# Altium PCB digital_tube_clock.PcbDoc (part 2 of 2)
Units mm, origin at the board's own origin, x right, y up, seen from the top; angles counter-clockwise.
Board outline 78.99 x 94.23 mm, 2 copper layers (Top Layer, Bottom Layer); 32 components, 49 nets, 189 pads, 6 vias.
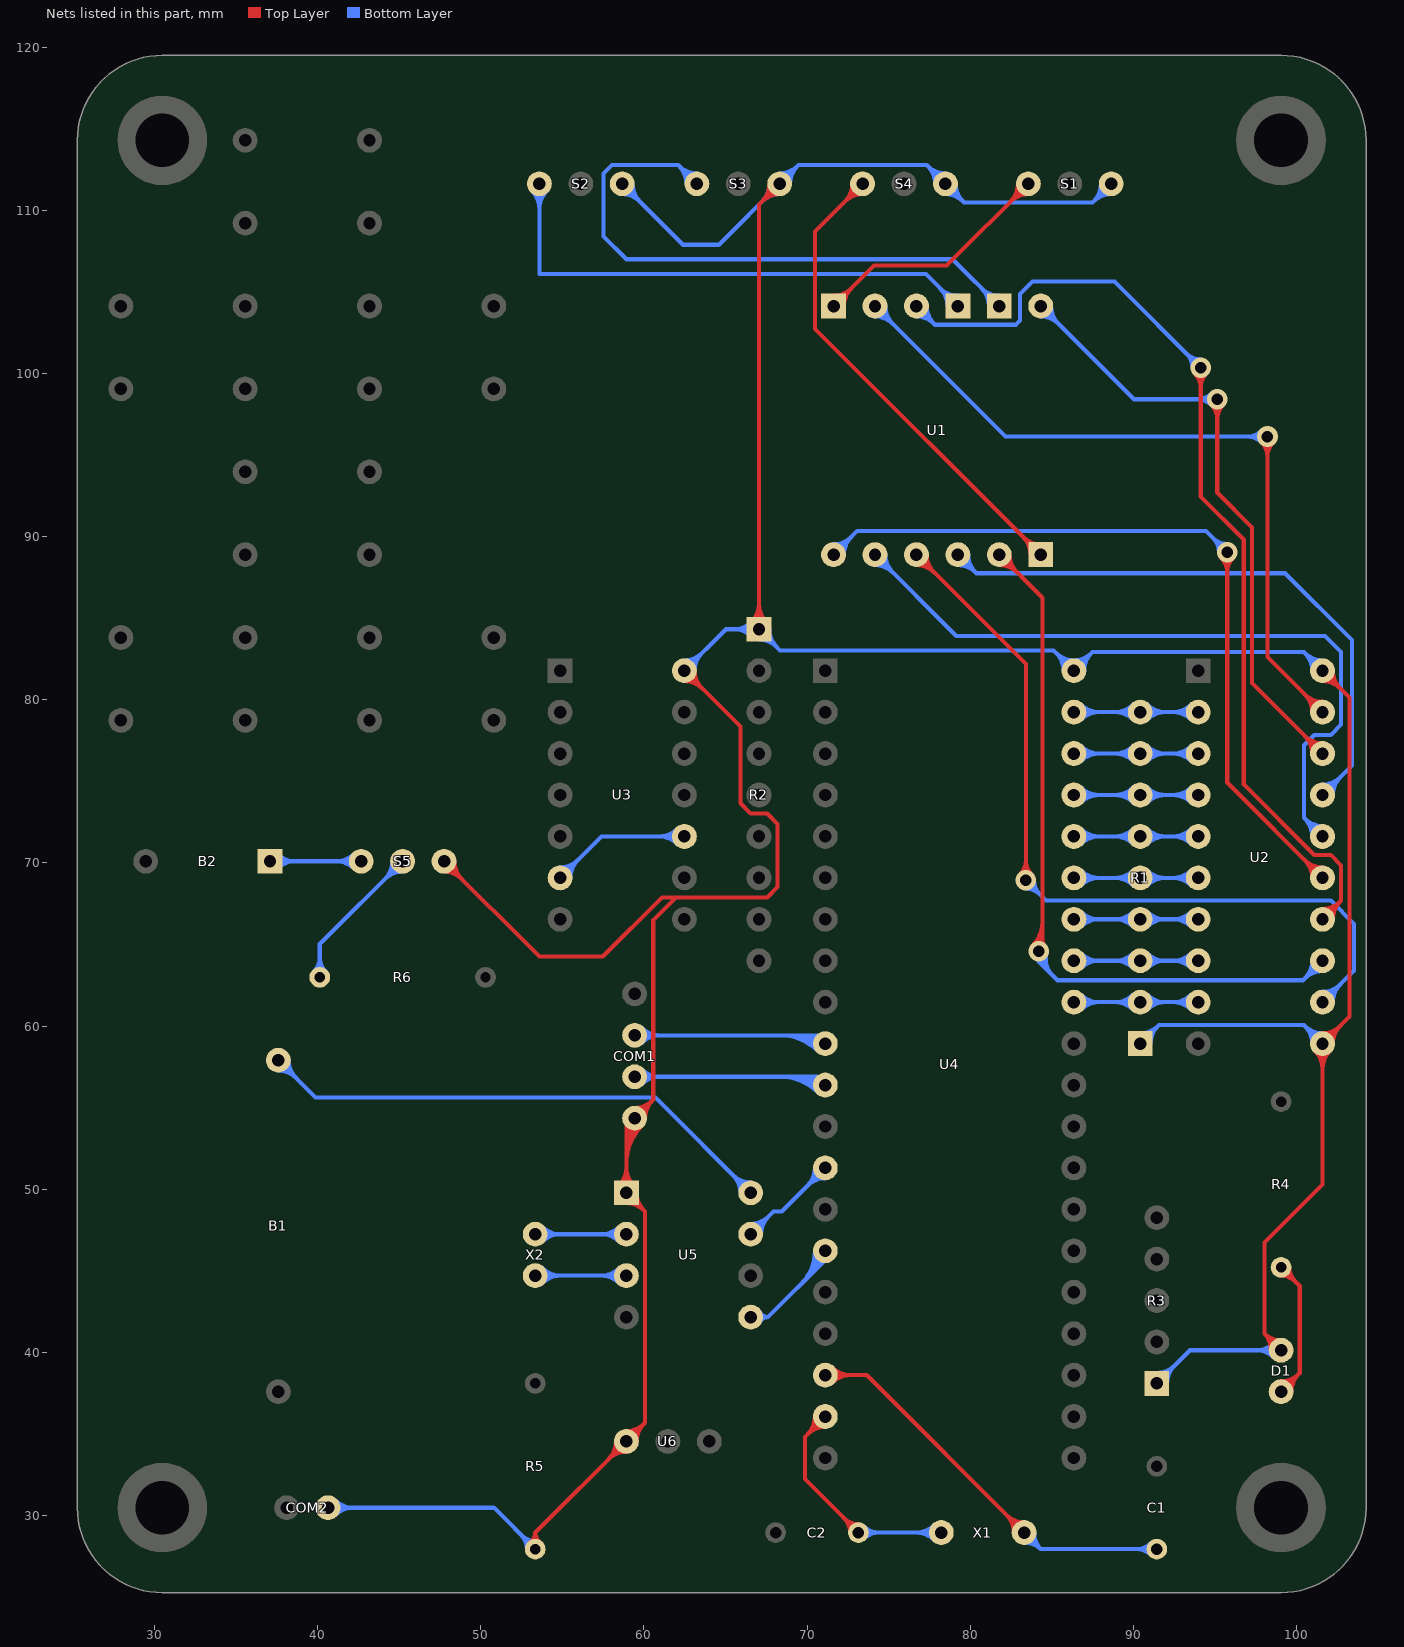
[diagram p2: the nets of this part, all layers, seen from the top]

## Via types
v1: diameter 1.27, hole 0.711, Top Layer to Bottom Layer, 6 vias

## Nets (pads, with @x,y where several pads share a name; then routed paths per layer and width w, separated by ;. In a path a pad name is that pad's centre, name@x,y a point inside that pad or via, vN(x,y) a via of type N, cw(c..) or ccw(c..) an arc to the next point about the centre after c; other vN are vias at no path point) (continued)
NetB1_VCC: B1.VCC U5.8 | length 40
  Bottom Layer w0.254: B1.VCC@37.592,57.277 cw(c37.592,55.744) 38.676,56.828 cw(c39.76,57.912) B1.VCC@38.227,57.912 ; B1.VCC@37.592,57.531 cw(c37.592,56.611) 38.242,57.262 cw(c38.893,57.912) B1.VCC@37.973,57.912 ; B1.VCC@37.592,57.912 39.878,55.626 60.706,55.626 U5.8@66.548,49.784 ; U5.8@65.913,49.784 ccw(c64.38,49.784) 65.464,50.868 ccw(c66.548,51.952) U5.8@66.548,50.419 ; U5.8@66.167,49.784 ccw(c65.247,49.784) 65.898,50.434 ccw(c66.548,51.085) U5.8@66.548,50.165
NetB2_1: B2.1 S5.e | length 13.3
  Bottom Layer w0.254: B2.1@37.084,70.104 S5.e@42.672,70.104 ; B2.1@37.353,69.835 cw(c38.004,69.184) 38.004,70.104 cw(c38.004,71.024) B2.1@37.353,70.373 ; B2.1@37.533,69.655 cw(c38.617,68.571) 38.617,70.104 cw(c38.617,71.637) B2.1@37.533,70.553 ; S5.e@42.223,69.655 ccw(c41.139,68.571) 41.139,70.104 ccw(c41.139,71.637) S5.e@42.223,70.553 ; S5.e@42.403,69.835 ccw(c41.752,69.184) 41.752,70.104 ccw(c41.752,71.024) S5.e@42.403,70.373
NetD1_2: D1.2 R4.1 | length 14.3
  Top Layer w0.254: D1.2@99.06,37.592 100.203,38.735 100.203,44.069 R4.1@99.06,45.212 ; D1.2@99.06,37.973 ccw(c99.06,38.893) 99.71,38.242 ccw(c100.361,37.592) D1.2@99.441,37.592 ; D1.2@99.06,38.227 ccw(c99.06,39.76) 100.144,38.676 ccw(c101.228,37.592) D1.2@99.695,37.592 ; R4.1@99.06,44.704 cw(c99.06,43.478) 99.927,44.345 cw(c100.794,45.212) R4.1@99.568,45.212
NetR1_2: R1.2 U2.9 U4.32 | length 23
  Bottom Layer w0.254: U4.32@86.36,61.468 R1.2@90.424,61.468 U2.9@93.98,61.468 ; U4.32@86.629,61.199 cw(c87.28,60.548) 87.28,61.468 cw(c87.28,62.388) U4.32@86.629,61.737 ; U4.32@86.809,61.019 cw(c87.893,59.935) 87.893,61.468 cw(c87.893,63.001) U4.32@86.809,61.917 ; R1.2@89.975,61.019 ccw(c88.891,59.935) 88.891,61.468 ccw(c88.891,63.001) R1.2@89.975,61.917 ; R1.2@90.155,61.199 ccw(c89.504,60.548) 89.504,61.468 ccw(c89.504,62.388) R1.2@90.155,61.737 ; R1.2@90.693,61.199 cw(c91.344,60.548) 91.344,61.468 cw(c91.344,62.388) R1.2@90.693,61.737 ; R1.2@90.873,61.019 cw(c91.957,59.935) 91.957,61.468 cw(c91.957,63.001) R1.2@90.873,61.917 ; U2.9@93.531,61.019 ccw(c92.447,59.935) 92.447,61.468 ccw(c92.447,63.001) U2.9@93.531,61.917 ; U2.9@93.711,61.199 ccw(c93.06,60.548) 93.06,61.468 ccw(c93.06,62.388) U2.9@93.711,61.737
NetR1_3: R1.3 U2.8 U4.33 | length 23
  Bottom Layer w0.254: U4.33@86.36,64.008 R1.3@90.424,64.008 U2.8@93.98,64.008 ; U4.33@86.629,63.739 cw(c87.28,63.088) 87.28,64.008 cw(c87.28,64.928) U4.33@86.629,64.277 ; U4.33@86.809,63.559 cw(c87.893,62.475) 87.893,64.008 cw(c87.893,65.541) U4.33@86.809,64.457 ; R1.3@89.975,63.559 ccw(c88.891,62.475) 88.891,64.008 ccw(c88.891,65.541) R1.3@89.975,64.457 ; R1.3@90.155,63.739 ccw(c89.504,63.088) 89.504,64.008 ccw(c89.504,64.928) R1.3@90.155,64.277 ; R1.3@90.693,63.739 cw(c91.344,63.088) 91.344,64.008 cw(c91.344,64.928) R1.3@90.693,64.277 ; R1.3@90.873,63.559 cw(c91.957,62.475) 91.957,64.008 cw(c91.957,65.541) R1.3@90.873,64.457 ; U2.8@93.531,63.559 ccw(c92.447,62.475) 92.447,64.008 ccw(c92.447,65.541) U2.8@93.531,64.457 ; U2.8@93.711,63.739 ccw(c93.06,63.088) 93.06,64.008 ccw(c93.06,64.928) U2.8@93.711,64.277
NetR1_4: R1.4 U2.7 U4.34 | length 23
  Bottom Layer w0.254: U4.34@86.36,66.548 R1.4@90.424,66.548 U2.7@93.98,66.548 ; U4.34@86.629,66.279 cw(c87.28,65.628) 87.28,66.548 cw(c87.28,67.468) U4.34@86.629,66.817 ; U4.34@86.809,66.099 cw(c87.893,65.015) 87.893,66.548 cw(c87.893,68.081) U4.34@86.809,66.997 ; R1.4@89.975,66.099 ccw(c88.891,65.015) 88.891,66.548 ccw(c88.891,68.081) R1.4@89.975,66.997 ; R1.4@90.155,66.279 ccw(c89.504,65.628) 89.504,66.548 ccw(c89.504,67.468) R1.4@90.155,66.817 ; R1.4@90.693,66.279 cw(c91.344,65.628) 91.344,66.548 cw(c91.344,67.468) R1.4@90.693,66.817 ; R1.4@90.873,66.099 cw(c91.957,65.015) 91.957,66.548 cw(c91.957,68.081) R1.4@90.873,66.997 ; U2.7@93.531,66.099 ccw(c92.447,65.015) 92.447,66.548 ccw(c92.447,68.081) U2.7@93.531,66.997 ; U2.7@93.711,66.279 ccw(c93.06,65.628) 93.06,66.548 ccw(c93.06,67.468) U2.7@93.711,66.817
NetR1_5: R1.5 U2.6 U4.35 | length 23
  Bottom Layer w0.254: U4.35@86.36,69.088 R1.5@90.424,69.088 U2.6@93.98,69.088 ; U4.35@86.629,68.819 cw(c87.28,68.168) 87.28,69.088 cw(c87.28,70.008) U4.35@86.629,69.357 ; U4.35@86.809,68.639 cw(c87.893,67.555) 87.893,69.088 cw(c87.893,70.621) U4.35@86.809,69.537 ; R1.5@89.975,68.639 ccw(c88.891,67.555) 88.891,69.088 ccw(c88.891,70.621) R1.5@89.975,69.537 ; R1.5@90.155,68.819 ccw(c89.504,68.168) 89.504,69.088 ccw(c89.504,70.008) R1.5@90.155,69.357 ; R1.5@90.693,68.819 cw(c91.344,68.168) 91.344,69.088 cw(c91.344,70.008) R1.5@90.693,69.357 ; R1.5@90.873,68.639 cw(c91.957,67.555) 91.957,69.088 cw(c91.957,70.621) R1.5@90.873,69.537 ; U2.6@93.531,68.639 ccw(c92.447,67.555) 92.447,69.088 ccw(c92.447,70.621) U2.6@93.531,69.537 ; U2.6@93.711,68.819 ccw(c93.06,68.168) 93.06,69.088 ccw(c93.06,70.008) U2.6@93.711,69.357
NetR1_6: R1.6 U2.5 U4.36 | length 23
  Bottom Layer w0.254: U4.36@86.36,71.628 R1.6@90.424,71.628 U2.5@93.98,71.628 ; U4.36@86.629,71.359 cw(c87.28,70.708) 87.28,71.628 cw(c87.28,72.548) U4.36@86.629,71.897 ; U4.36@86.809,71.179 cw(c87.893,70.095) 87.893,71.628 cw(c87.893,73.161) U4.36@86.809,72.077 ; R1.6@89.975,71.179 ccw(c88.891,70.095) 88.891,71.628 ccw(c88.891,73.161) R1.6@89.975,72.077 ; R1.6@90.155,71.359 ccw(c89.504,70.708) 89.504,71.628 ccw(c89.504,72.548) R1.6@90.155,71.897 ; R1.6@90.693,71.359 cw(c91.344,70.708) 91.344,71.628 cw(c91.344,72.548) R1.6@90.693,71.897 ; R1.6@90.873,71.179 cw(c91.957,70.095) 91.957,71.628 cw(c91.957,73.161) R1.6@90.873,72.077 ; U2.5@93.531,71.179 ccw(c92.447,70.095) 92.447,71.628 ccw(c92.447,73.161) U2.5@93.531,72.077 ; U2.5@93.711,71.359 ccw(c93.06,70.708) 93.06,71.628 ccw(c93.06,72.548) U2.5@93.711,71.897
NetR1_7: R1.7 U2.4 U4.37 | length 23
  Bottom Layer w0.254: U4.37@86.36,74.168 R1.7@90.424,74.168 U2.4@93.98,74.168 ; U4.37@86.629,73.899 cw(c87.28,73.248) 87.28,74.168 cw(c87.28,75.088) U4.37@86.629,74.437 ; U4.37@86.809,73.719 cw(c87.893,72.635) 87.893,74.168 cw(c87.893,75.701) U4.37@86.809,74.617 ; R1.7@89.975,73.719 ccw(c88.891,72.635) 88.891,74.168 ccw(c88.891,75.701) R1.7@89.975,74.617 ; R1.7@90.155,73.899 ccw(c89.504,73.248) 89.504,74.168 ccw(c89.504,75.088) R1.7@90.155,74.437 ; R1.7@90.693,73.899 cw(c91.344,73.248) 91.344,74.168 cw(c91.344,75.088) R1.7@90.693,74.437 ; R1.7@90.873,73.719 cw(c91.957,72.635) 91.957,74.168 cw(c91.957,75.701) R1.7@90.873,74.617 ; U2.4@93.531,73.719 ccw(c92.447,72.635) 92.447,74.168 ccw(c92.447,75.701) U2.4@93.531,74.617 ; U2.4@93.711,73.899 ccw(c93.06,73.248) 93.06,74.168 ccw(c93.06,75.088) U2.4@93.711,74.437
NetR1_8: R1.8 U2.3 U4.38 | length 23
  Bottom Layer w0.254: U4.38@86.36,76.708 R1.8@90.424,76.708 U2.3@93.98,76.708 ; U4.38@86.629,76.439 cw(c87.28,75.788) 87.28,76.708 cw(c87.28,77.628) U4.38@86.629,76.977 ; U4.38@86.809,76.259 cw(c87.893,75.175) 87.893,76.708 cw(c87.893,78.241) U4.38@86.809,77.157 ; R1.8@89.975,76.259 ccw(c88.891,75.175) 88.891,76.708 ccw(c88.891,78.241) R1.8@89.975,77.157 ; R1.8@90.155,76.439 ccw(c89.504,75.788) 89.504,76.708 ccw(c89.504,77.628) R1.8@90.155,76.977 ; R1.8@90.693,76.439 cw(c91.344,75.788) 91.344,76.708 cw(c91.344,77.628) R1.8@90.693,76.977 ; R1.8@90.873,76.259 cw(c91.957,75.175) 91.957,76.708 cw(c91.957,78.241) R1.8@90.873,77.157 ; U2.3@93.531,76.259 ccw(c92.447,75.175) 92.447,76.708 ccw(c92.447,78.241) U2.3@93.531,77.157 ; U2.3@93.711,76.439 ccw(c93.06,75.788) 93.06,76.708 ccw(c93.06,77.628) U2.3@93.711,76.977
NetR1_9: R1.9 U2.2 U4.39 | length 23
  Bottom Layer w0.254: U4.39@86.36,79.248 R1.9@90.424,79.248 U2.2@93.98,79.248 ; U4.39@86.629,78.979 cw(c87.28,78.328) 87.28,79.248 cw(c87.28,80.168) U4.39@86.629,79.517 ; U4.39@86.809,78.799 cw(c87.893,77.715) 87.893,79.248 cw(c87.893,80.781) U4.39@86.809,79.697 ; R1.9@89.975,78.799 ccw(c88.891,77.715) 88.891,79.248 ccw(c88.891,80.781) R1.9@89.975,79.697 ; R1.9@90.155,78.979 ccw(c89.504,78.328) 89.504,79.248 ccw(c89.504,80.168) R1.9@90.155,79.517 ; R1.9@90.693,78.979 cw(c91.344,78.328) 91.344,79.248 cw(c91.344,80.168) R1.9@90.693,79.517 ; R1.9@90.873,78.799 cw(c91.957,77.715) 91.957,79.248 cw(c91.957,80.781) R1.9@90.873,79.697 ; U2.2@93.531,78.799 ccw(c92.447,77.715) 92.447,79.248 ccw(c92.447,80.781) U2.2@93.531,79.697 ; U2.2@93.711,78.979 ccw(c93.06,78.328) 93.06,79.248 ccw(c93.06,80.168) U2.2@93.711,79.517
NetR6_2: R6.2 S5.b | length 15
  Bottom Layer w0.254: R6.2@39.773,63.351 ccw(c38.906,64.218) 40.132,64.218 ccw(c41.358,64.218) R6.2@40.491,63.351 ; R6.2@40.132,62.992 40.132,65.024 S5.b@45.212,70.104 ; S5.b@44.577,70.104 cw(c43.044,70.104) 44.128,69.02 cw(c45.212,67.936) S5.b@45.212,69.469 ; S5.b@44.831,70.104 cw(c43.911,70.104) 44.562,69.454 cw(c45.212,68.803) S5.b@45.212,69.723
NetU1_a: U1.a U2.19 | length 57.2
  Top Layer w0.254: v1@97.863,95.78 cw(c96.995,94.913) 98.222,94.913 cw(c99.448,94.913) v1@98.581,95.78 ; v1(98.222,96.139) 98.222,82.626 U2.19@101.6,79.248 ; U2.19@100.965,79.248 ccw(c99.432,79.248) 100.516,80.332 ccw(c101.6,81.416) U2.19@101.6,79.883 ; U2.19@101.219,79.248 ccw(c100.299,79.248) 100.95,79.898 ccw(c101.6,80.549) U2.19@101.6,79.629
  Bottom Layer w0.254: U1.a@74.168,103.505 cw(c74.168,101.972) 75.252,103.056 cw(c76.336,104.14) U1.a@74.803,104.14 ; U1.a@74.168,103.759 cw(c74.168,102.839) 74.818,103.49 cw(c75.469,104.14) U1.a@74.549,104.14 ; U1.a@74.168,104.14 82.169,96.139 v1(98.222,96.139) ; v1@97.863,95.78 ccw(c96.995,94.913) 96.995,96.139 ccw(c96.995,97.365) v1@97.863,96.498
NetU1_b: U1.b U2.18 | length 49.1
  Top Layer w0.254: v1@94.789,98.066 cw(c93.922,97.199) 95.148,97.199 cw(c96.375,97.199) v1@95.508,98.066 ; v1(95.148,98.425) 95.148,92.71 97.282,90.576 97.282,81.026 U2.18@101.6,76.708 ; U2.18@100.965,76.708 ccw(c99.432,76.708) 100.516,77.792 ccw(c101.6,78.876) U2.18@101.6,77.343 ; U2.18@101.219,76.708 ccw(c100.299,76.708) 100.95,77.358 ccw(c101.6,78.009) U2.18@101.6,77.089
  Bottom Layer w0.254: U1.b@84.328,103.505 cw(c84.328,101.972) 85.412,103.056 cw(c86.496,104.14) U1.b@84.963,104.14 ; U1.b@84.328,103.759 cw(c84.328,102.839) 84.978,103.49 cw(c85.629,104.14) U1.b@84.709,104.14 ; U1.b@84.328,104.14 90.043,98.425 v1(95.148,98.425) ; v1@94.789,98.066 ccw(c93.922,97.199) 93.922,98.425 ccw(c93.922,99.651) v1@94.789,98.784
NetU1_c: U1.c U2.17 | length 44.3
  Bottom Layer w0.254: U1.c@79.248,88.265 cw(c79.248,86.732) 80.332,87.816 cw(c81.416,88.9) U1.c@79.883,88.9 ; U1.c@79.248,88.519 cw(c79.248,87.599) 79.898,88.25 cw(c80.549,88.9) U1.c@79.629,88.9 ; U1.c@79.248,88.9 80.391,87.757 99.314,87.757 103.403,83.668 103.403,75.971 U2.17@101.6,74.168 ; U2.17@101.6,74.549 ccw(c101.6,75.469) 102.25,74.818 ccw(c102.901,74.168) U2.17@101.981,74.168 ; U2.17@101.6,74.803 ccw(c101.6,76.336) 102.684,75.252 ccw(c103.768,74.168) U2.17@102.235,74.168
NetU1_d: U1.d U2.16 | length 52.1
  Bottom Layer w0.254: U1.d@74.168,88.265 cw(c74.168,86.732) 75.252,87.816 cw(c76.336,88.9) U1.d@74.803,88.9 ; U1.d@74.168,88.519 cw(c74.168,87.599) 74.818,88.25 cw(c75.469,88.9) U1.d@74.549,88.9 ; U1.d@74.168,88.9 79.146,83.922 101.752,83.922 102.743,82.931 102.743,78.486 102.108,77.851 101.092,77.851 100.457,77.216 100.457,72.771 U2.16@101.6,71.628 ; U2.16@100.965,71.628 ccw(c99.432,71.628) 100.516,72.712 ccw(c101.6,73.796) U2.16@101.6,72.263 ; U2.16@101.219,71.628 ccw(c100.299,71.628) 100.95,72.278 ccw(c101.6,72.929) U2.16@101.6,72.009
NetU1_e: U1.e U2.15 | length 59.2
  Top Layer w0.254: v1@95.399,88.693 cw(c94.532,87.826) 95.758,87.826 cw(c96.984,87.826) v1@96.117,88.693 ; v1(95.758,89.052) 95.758,74.93 U2.15@101.6,69.088 ; U2.15@100.965,69.088 ccw(c99.432,69.088) 100.516,70.172 ccw(c101.6,71.256) U2.15@101.6,69.723 ; U2.15@101.219,69.088 ccw(c100.299,69.088) 100.95,69.738 ccw(c101.6,70.389) U2.15@101.6,69.469
  Bottom Layer w0.254: U1.e@71.628,88.9 73.076,90.348 94.463,90.348 v1(95.758,89.052) ; U1.e@71.628,89.281 ccw(c71.628,90.201) 72.278,89.55 ccw(c72.929,88.9) U1.e@72.009,88.9 ; U1.e@71.628,89.535 ccw(c71.628,91.068) 72.712,89.984 ccw(c73.796,88.9) U1.e@72.263,88.9 ; v1@95.25,89.052 ccw(c94.024,89.052) 94.891,89.92 ccw(c95.758,90.787) v1@95.758,89.56
NetU1_f: U1.f U2.14 | length 72.1
  Top Layer w0.254: v1@93.773,99.996 cw(c92.906,99.129) 94.132,99.129 cw(c95.359,99.129) v1@94.492,99.996 ; v1(94.132,100.355) 94.132,92.456 96.774,89.814 96.774,74.803 101.092,70.485 102.108,70.485 102.743,69.85 102.743,67.691 U2.14@101.6,66.548 ; U2.14@101.6,66.929 ccw(c101.6,67.849) 102.25,67.198 ccw(c102.901,66.548) U2.14@101.981,66.548 ; U2.14@101.6,67.183 ccw(c101.6,68.716) 102.684,67.632 ccw(c103.768,66.548) U2.14@102.235,66.548
  Bottom Layer w0.254: U1.f@76.708,103.505 cw(c76.708,101.972) 77.792,103.056 cw(c78.876,104.14) U1.f@77.343,104.14 ; U1.f@76.708,103.759 cw(c76.708,102.839) 77.358,103.49 cw(c78.009,104.14) U1.f@77.089,104.14 ; U1.f@76.708,104.14 77.851,102.997 82.804,102.997 83.058,103.251 83.058,104.877 83.82,105.639 88.849,105.639 v1(94.132,100.355) ; v1@93.624,100.355 ccw(c92.398,100.355) 93.265,101.223 ccw(c94.132,102.09) v1@94.132,100.863
NetU1_g: U1.g U2.13 | length 58.8
  Top Layer w0.254: U1.g@81.788,88.265 cw(c81.788,86.732) 82.872,87.816 cw(c83.956,88.9) U1.g@82.423,88.9 ; U1.g@81.788,88.519 cw(c81.788,87.599) 82.438,88.25 cw(c83.089,88.9) U1.g@82.169,88.9 ; U1.g@81.788,88.9 84.43,86.258 84.43,64.821 v1(84.201,64.592) ; v1@83.842,64.951 ccw(c82.423,66.371) 84.43,66.371 ; v1@84.021,64.772 ccw(c83.036,65.757) 84.43,65.757 ; 84.43,65.267 ccw(c84.876,65.267) v1@84.56,64.951
  Bottom Layer w0.254: 84.42,63.738 cw(c85.031,64.35) v1(84.201,64.592) 84.201,63.957 85.344,62.814 100.406,62.814 U2.13@101.6,64.008 ; v1@84.445,64.521 ccw(c85.501,64.213) 84.723,63.435 ; v1@84.689,64.45 ccw(c85.971,64.076) 85.026,63.132 ; U2.13@100.965,64.008 cw(c99.432,64.008) 100.516,62.924 cw(c101.6,61.84) U2.13@101.6,63.373 ; U2.13@101.219,64.008 cw(c100.299,64.008) 100.95,63.358 cw(c101.6,62.707) U2.13@101.6,63.627
NetU1_h: U1.h U2.12 | length 61.1
  Top Layer w0.254: U1.h@76.708,88.265 cw(c76.708,86.732) 77.792,87.816 cw(c78.876,88.9) U1.h@77.343,88.9 ; U1.h@76.708,88.519 cw(c76.708,87.599) 77.358,88.25 cw(c78.009,88.9) U1.h@77.089,88.9 ; U1.h@76.708,88.9 83.414,82.194 v1(83.414,68.936) ; v1@83.054,69.295 ccw(c82.187,70.162) 83.414,70.162 ccw(c84.64,70.162) v1@83.773,69.295
  Bottom Layer w0.254: v1@83.414,68.428 cw(c83.414,67.201) 84.281,68.068 cw(c85.148,68.936) v1@83.922,68.936 ; v1(83.414,68.936) 84.658,67.691 102.108,67.691 103.53,66.269 103.53,63.398 U2.12@101.6,61.468 ; U2.12@101.6,61.849 ccw(c101.6,62.769) 102.25,62.118 ccw(c102.901,61.468) U2.12@101.981,61.468 ; U2.12@101.6,62.103 ccw(c101.6,63.636) 102.684,62.552 ccw(c103.768,61.468) U2.12@102.235,61.468
NetU5_2: U5.2 X2.2 | length 13.3
  Bottom Layer w0.254: X2.2@53.34,47.244 U5.2@58.928,47.244 ; X2.2@53.609,46.975 cw(c54.26,46.324) 54.26,47.244 cw(c54.26,48.164) X2.2@53.609,47.513 ; X2.2@53.789,46.795 cw(c54.873,45.711) 54.873,47.244 cw(c54.873,48.777) X2.2@53.789,47.693 ; U5.2@58.479,46.795 ccw(c57.395,45.711) 57.395,47.244 ccw(c57.395,48.777) U5.2@58.479,47.693 ; U5.2@58.659,46.975 ccw(c58.008,46.324) 58.008,47.244 ccw(c58.008,48.164) U5.2@58.659,47.513
NetU5_3: U5.3 X2.1 | length 13.3
  Bottom Layer w0.254: X2.1@53.34,44.704 U5.3@58.928,44.704 ; X2.1@53.609,44.435 cw(c54.26,43.784) 54.26,44.704 cw(c54.26,45.624) X2.1@53.609,44.973 ; X2.1@53.789,44.255 cw(c54.873,43.171) 54.873,44.704 cw(c54.873,46.237) X2.1@53.789,45.153 ; U5.3@58.479,44.255 ccw(c57.395,43.171) 57.395,44.704 ccw(c57.395,46.237) U5.3@58.479,45.153 ; U5.3@58.659,44.435 ccw(c58.008,43.784) 58.008,44.704 ccw(c58.008,45.624) U5.3@58.659,44.973
RST: U4.15 U5.5 | length 13.2
  Bottom Layer w0.254: U5.5@66.548,42.164 67.615,42.164 ; U5.5@67.106,41.861 cw(c67.615,41.585) 67.615,42.164 ; U5.5@67.106,42.467 ccw(c67.615,42.743) 67.615,42.164 ; 69.641,44.19 ccw(c67.603,46.228) U4.15@70.485,46.228 ; 70.074,44.624 ccw(c68.47,46.228) U4.15@70.739,46.228 ; 70.508,45.057 ccw(c69.337,46.228) U4.15@70.993,46.228 ; U4.15@71.12,46.228 71.12,45.669 67.615,42.164
RX: COM1.RX U4.11 | length 23.1
  Bottom Layer w0.254: COM1.RX@59.436,56.896 70.612,56.896 U4.11@71.12,56.388 ; COM1.RX@59.705,56.627 cw(c60.356,55.976) 60.356,56.896 cw(c60.356,57.816) COM1.RX@59.705,57.165 ; COM1.RX@59.885,56.447 cw(c60.969,55.363) 60.969,56.896 cw(c60.969,58.429) COM1.RX@59.885,57.345 ; 68.361,56.896 cw(c68.361,53.629) U4.11@70.671,55.939 ; 68.974,56.896 cw(c68.974,54.242) U4.11@70.851,56.119 ; 69.587,56.896 cw(c69.587,54.855) U4.11@71.03,56.298 ; 70.2,56.896 cw(c70.2,55.468) U4.11@71.21,56.478
SCLK: U4.13 U5.7 | length 14
  Bottom Layer w0.254: U5.7@66.548,47.244 67.945,48.641 68.453,48.641 U4.13@71.12,51.308 ; U5.7@66.548,47.625 ccw(c66.548,48.545) 67.198,47.894 ccw(c67.849,47.244) U5.7@66.929,47.244 ; U5.7@66.548,47.879 ccw(c66.548,49.412) 67.632,48.328 ccw(c68.716,47.244) U5.7@67.183,47.244 ; U4.13@70.485,51.308 cw(c68.952,51.308) 70.036,50.224 cw(c71.12,49.14) U4.13@71.12,50.673 ; U4.13@70.739,51.308 cw(c69.819,51.308) 70.47,50.658 cw(c71.12,50.007) U4.13@71.12,50.927
TUBE1: S1.e U1.1 | length 22.7
  Top Layer w0.254: U1.1@71.628,104.14 74.117,106.629 78.562,106.629 S1.e@83.566,111.633 ; U1.1@71.628,104.521 ccw(c71.628,105.441) 72.278,104.79 ccw(c72.929,104.14) U1.1@72.009,104.14 ; U1.1@71.628,104.775 ccw(c71.628,106.308) 72.712,105.224 ccw(c73.796,104.14) U1.1@72.263,104.14 ; S1.e@82.931,111.633 cw(c81.398,111.633) 82.482,110.549 cw(c83.566,109.465) S1.e@83.566,110.998 ; S1.e@83.185,111.633 cw(c82.265,111.633) 82.916,110.983 cw(c83.566,110.332) S1.e@83.566,111.252
TUBE2: S2.e U1.2 | length 39.7
  Bottom Layer w0.254: S2.e@53.145,111.184 cw(c52.061,110.1) 53.594,110.1 cw(c55.127,110.1) S2.e@54.043,111.184 ; S2.e@53.325,111.364 cw(c52.674,110.713) 53.594,110.713 cw(c54.514,110.713) S2.e@53.863,111.364 ; S2.e@53.594,111.633 53.594,106.121 53.619,106.096 77.292,106.096 U1.2@79.248,104.14 ; U1.2@78.613,104.14 ccw(c77.08,104.14) 78.164,105.224 ccw(c79.248,106.308) U1.2@79.248,104.775 ; U1.2@78.867,104.14 ccw(c77.947,104.14) 78.598,104.79 ccw(c79.248,105.441) U1.2@79.248,104.521
TUBE3: S3.e U1.3 | length 44
  Bottom Layer w0.254: S3.e@62.611,111.633 ccw(c61.078,111.633) 62.162,112.717 ccw(c63.246,113.801) S3.e@63.246,112.268 ; S3.e@62.865,111.633 ccw(c61.945,111.633) 62.596,112.283 ccw(c63.246,112.934) S3.e@63.246,112.014 ; S3.e@63.246,111.633 62.103,112.776 58.039,112.776 57.531,112.268 57.531,108.407 58.928,107.01 78.918,107.01 U1.3@81.788,104.14 ; U1.3@81.153,104.14 ccw(c79.62,104.14) 80.704,105.224 ccw(c81.788,106.308) U1.3@81.788,104.775 ; U1.3@81.407,104.14 ccw(c80.487,104.14) 81.138,104.79 ccw(c81.788,105.441) U1.3@81.788,104.521
TUBE4: S4.e U1.4 | length 37.4
  Top Layer w0.254: S4.e@72.771,111.633 cw(c71.238,111.633) 72.322,110.549 cw(c73.406,109.465) S4.e@73.406,110.998 ; S4.e@73.025,111.633 cw(c72.105,111.633) 72.756,110.983 cw(c73.406,110.332) S4.e@73.406,111.252 ; S4.e@73.406,111.633 70.485,108.712 70.485,102.743 U1.4@84.328,88.9 ; U1.4@83.693,88.9 ccw(c82.16,88.9) 83.244,89.984 ccw(c84.328,91.068) U1.4@84.328,89.535 ; U1.4@83.947,88.9 ccw(c83.027,88.9) 83.678,89.55 ccw(c84.328,90.201) U1.4@84.328,89.281
TX: COM1.TX U4.10 | length 23.1
  Bottom Layer w0.254: COM1.TX@59.436,59.436 70.612,59.436 U4.10@71.12,58.928 ; COM1.TX@59.705,59.167 cw(c60.356,58.516) 60.356,59.436 cw(c60.356,60.356) COM1.TX@59.705,59.705 ; COM1.TX@59.885,58.987 cw(c60.969,57.903) 60.969,59.436 cw(c60.969,60.969) COM1.TX@59.885,59.885 ; 68.361,59.436 cw(c68.361,56.169) U4.10@70.671,58.479 ; 68.974,59.436 cw(c68.974,56.782) U4.10@70.851,58.659 ; 69.587,59.436 cw(c69.587,57.395) U4.10@71.03,58.838 ; 70.2,59.436 cw(c70.2,58.008) U4.10@71.21,59.018
VCC: COM1.VCC COM2.VCC D1.1 R1.1 R2.1 R3.1 R5.2 S1.c S2.c S3.c S4.c S5.c U2.11 U2.20 U3.14 U4.40 U5.1 U6.VDD | length 395.5
  Top Layer w0.254: S5.c@47.752,69.469 cw(c47.752,67.936) 48.836,69.02 cw(c49.92,70.104) S5.c@48.387,70.104 ; S5.c@47.752,69.723 cw(c47.752,68.803) 48.402,69.454 cw(c49.053,70.104) S5.c@48.133,70.104 ; S5.c@47.752,70.104 53.594,64.262 57.48,64.262 61.112,67.894 61.976,67.894 ; R5.2@53.035,28.346 ccw(c52.578,28.956) 53.34,28.956 ; R5.2@53.34,27.94 53.34,28.956 ; R5.2@53.645,28.346 cw(c54.102,28.956) 53.34,28.956 ; U6.VDD@58.293,34.544 cw(c56.76,34.544) 57.844,33.46 cw(c58.928,32.376) U6.VDD@58.928,33.909 ; U5.1@58.479,50.233 ccw(c57.395,51.317) 58.928,51.317 ccw(c60.461,51.317) U5.1@59.377,50.233 ; U6.VDD@58.547,34.544 cw(c57.627,34.544) 58.278,33.894 cw(c58.928,33.243) U6.VDD@58.928,34.163 ; U5.1@58.659,50.053 ccw(c58.008,50.704) 58.928,50.704 ccw(c59.848,50.704) U5.1@59.197,50.053 ; U6.VDD@58.928,34.925 ccw(c58.928,35.845) 59.578,35.194 ccw(c60.229,34.544) U6.VDD@59.309,34.544 ; U6.VDD@58.928,35.179 ccw(c58.928,36.712) 60.012,35.628 ccw(c61.096,34.544) U6.VDD@59.563,34.544 ; U5.1@58.928,49.149 cw(c58.928,47.616) 60.012,48.7 cw(c61.096,49.784) U5.1@59.563,49.784 ; U5.1@58.928,49.403 cw(c58.928,48.483) 59.578,49.134 cw(c60.229,49.784) U5.1@59.309,49.784 ; 58.928,51.597 cw(c62.195,51.597) COM1.VCC@59.885,53.907 ; 58.928,52.21 cw(c61.582,52.21) COM1.VCC@59.705,54.087 ; 58.928,52.823 cw(c60.969,52.823) COM1.VCC@59.526,54.266 ; 58.928,53.436 cw(c60.356,53.436) COM1.VCC@59.346,54.446 ; COM1.VCC@59.436,54.737 ccw(c59.436,55.657) 60.086,55.006 ccw(c60.737,54.356) COM1.VCC@59.817,54.356 ; COM1.VCC@59.436,54.991 ccw(c59.436,56.524) 60.52,55.44 ccw(c61.604,54.356) COM1.VCC@60.071,54.356 ; U3.14@62.484,81.153 cw(c62.484,79.62) 63.568,80.704 cw(c64.652,81.788) U3.14@63.119,81.788 ; U3.14@62.484,81.407 cw(c62.484,80.487) 63.134,81.138 cw(c63.785,81.788) U3.14@62.865,81.788 ; U3.14@62.484,81.788 65.913,78.359 65.913,73.66 66.548,73.025 67.564,73.025 68.199,72.39 68.199,68.529 67.564,67.894 61.976,67.894 ; R2.1@66.607,84.777 ccw(c65.523,85.861) 67.056,85.861 ccw(c68.589,85.861) R2.1@67.505,84.777 ; R2.1@66.787,84.597 ccw(c66.136,85.248) 67.056,85.248 ccw(c67.976,85.248) R2.1@67.325,84.597 ; R2.1@67.056,84.328 67.056,110.363 S3.c@68.326,111.633 ; S3.c@67.691,111.633 cw(c66.158,111.633) 67.242,110.549 cw(c68.326,109.465) S3.c@68.326,110.998 ; S3.c@67.945,111.633 cw(c67.025,111.633) 67.676,110.983 cw(c68.326,110.332) S3.c@68.326,111.252 ; D1.1@98.426,40.162 ccw(c97.119,40.223) 98.044,41.148 ; D1.1@98.679,40.15 ccw(c97.896,40.187) 98.45,40.742 ccw(c99.005,41.296) D1.1@99.042,40.513 ; D1.1@99.03,40.766 cw(c98.969,42.073) 98.044,41.148 ; D1.1@99.06,40.132 98.044,41.148 ; U2.11@101.151,58.479 cw(c100.067,57.395) 101.6,57.395 cw(c103.133,57.395) U2.11@102.049,58.479 ; U2.11@101.331,58.659 cw(c100.68,58.008) 101.6,58.008 cw(c102.52,58.008) U2.11@101.869,58.659 ; U2.11@101.6,59.309 ccw(c101.6,60.229) 102.25,59.578 ccw(c102.901,58.928) U2.11@101.981,58.928 ; U2.11@101.6,59.563 ccw(c101.6,61.096) 102.684,60.012 ccw(c103.768,58.928) U2.11@102.235,58.928 ; U2.20@101.6,81.153 cw(c101.6,79.62) 102.684,80.704 cw(c103.768,81.788) U2.20@102.235,81.788 ; U2.20@101.6,81.407 cw(c101.6,80.487) 102.25,81.138 cw(c102.901,81.788) U2.20@101.981,81.788 ; U2.20@101.6,81.788 103.251,80.137 103.251,60.579 U2.11@101.6,58.928 101.6,50.292 98.044,46.736 98.044,41.148 ; 53.34,28.956 U6.VDD@58.928,34.544 60.071,35.687 60.071,48.641 U5.1@58.928,49.784 58.928,53.848 COM1.VCC@59.436,54.356 60.579,55.499 60.579,66.497 61.976,67.894
  Bottom Layer w0.254: COM2.VCC@40.64,30.48 50.8,30.48 R5.2@53.34,27.94 ; COM2.VCC@40.909,30.211 cw(c41.56,29.56) 41.56,30.48 cw(c41.56,31.4) COM2.VCC@40.909,30.749 ; COM2.VCC@41.089,30.031 cw(c42.173,28.947) 42.173,30.48 cw(c42.173,32.013) COM2.VCC@41.089,30.929 ; R5.2@52.832,27.94 ccw(c51.606,27.94) 52.473,28.807 ccw(c53.34,29.674) R5.2@53.34,28.448 ; S2.c@58.674,110.998 cw(c58.674,109.465) 59.758,110.549 cw(c60.842,111.633) S2.c@59.309,111.633 ; S2.c@58.674,111.252 cw(c58.674,110.332) 59.324,110.983 cw(c59.975,111.633) S2.c@59.055,111.633 ; S2.c@58.674,111.633 62.408,107.899 64.592,107.899 S3.c@68.326,111.633 69.469,112.776 77.343,112.776 S4.c@78.486,111.633 79.629,110.49 87.503,110.49 S1.c@88.646,111.633 ; U3.14@62.484,81.788 65.024,84.328 R2.1@67.056,84.328 68.351,83.033 85.115,83.033 U4.40@86.36,81.788 87.503,82.931 100.457,82.931 U2.20@101.6,81.788 ; U3.14@62.484,82.169 ccw(c62.484,83.089) 63.134,82.438 ccw(c63.785,81.788) U3.14@62.865,81.788 ; U3.14@62.484,82.423 ccw(c62.484,83.956) 63.568,82.872 ccw(c64.652,81.788) U3.14@63.119,81.788 ; R2.1@66.607,83.879 ccw(c65.523,82.795) 65.523,84.328 ccw(c65.523,85.861) R2.1@66.607,84.777 ; R2.1@66.787,84.059 ccw(c66.136,83.408) 66.136,84.328 ccw(c66.136,85.248) R2.1@66.787,84.597 ; R2.1@67.056,83.693 cw(c67.056,82.16) 68.14,83.244 cw(c69.224,84.328) R2.1@67.691,84.328 ; R2.1@67.056,83.947 cw(c67.056,83.027) 67.706,83.678 cw(c68.357,84.328) R2.1@67.437,84.328 ; S3.c@67.691,111.633 cw(c66.158,111.633) 67.242,110.549 cw(c68.326,109.465) S3.c@68.326,110.998 ; S3.c@67.945,111.633 cw(c67.025,111.633) 67.676,110.983 cw(c68.326,110.332) S3.c@68.326,111.252 ; S3.c@68.326,112.014 ccw(c68.326,112.934) 68.976,112.283 ccw(c69.627,111.633) S3.c@68.707,111.633 ; S3.c@68.326,112.268 ccw(c68.326,113.801) 69.41,112.717 ccw(c70.494,111.633) S3.c@68.961,111.633 ; S4.c@77.851,111.633 ccw(c76.318,111.633) 77.402,112.717 ccw(c78.486,113.801) S4.c@78.486,112.268 ; S4.c@78.105,111.633 ccw(c77.185,111.633) 77.836,112.283 ccw(c78.486,112.934) S4.c@78.486,112.014 ; S4.c@78.486,110.998 cw(c78.486,109.465) 79.57,110.549 cw(c80.654,111.633) S4.c@79.121,111.633 ; S4.c@78.486,111.252 cw(c78.486,110.332) 79.136,110.983 cw(c79.787,111.633) S4.c@78.867,111.633 ; U4.40@85.725,81.788 ccw(c84.192,81.788) 85.276,82.872 ccw(c86.36,83.956) 86.36,82.423 ccw(c86.36,83.956) 87.444,82.872 ccw(c88.528,81.788) U4.40@86.995,81.788 ; U4.40@85.979,81.788 ccw(c85.059,81.788) 85.71,82.438 ccw(c86.36,83.089) 86.36,82.169 ccw(c86.36,83.089) 87.01,82.438 ccw(c87.661,81.788) U4.40@86.741,81.788 ; S1.c@88.011,111.633 cw(c86.478,111.633) 87.562,110.549 cw(c88.646,109.465) S1.c@88.646,110.998 ; S1.c@88.265,111.633 cw(c87.345,111.633) 87.996,110.983 cw(c88.646,110.332) S1.c@88.646,111.252 ; R1.1@90.424,58.928 91.567,60.071 100.457,60.071 U2.11@101.6,58.928 ; R1.1@90.424,59.309 ccw(c90.424,60.229) 91.074,59.578 ccw(c91.725,58.928) R1.1@90.805,58.928 ; R1.1@90.424,59.563 ccw(c90.424,61.096) 91.508,60.012 ccw(c92.592,58.928) R1.1@91.059,58.928 ; R3.1@91.44,38.1 93.472,40.132 D1.1@99.06,40.132 ; R3.1@91.44,38.481 ccw(c91.44,39.401) 92.09,38.75 ccw(c92.741,38.1) R3.1@91.821,38.1 ; R3.1@91.44,38.735 ccw(c91.44,40.268) 92.524,39.184 ccw(c93.608,38.1) R3.1@92.075,38.1 ; D1.1@98.611,39.683 ccw(c97.527,38.599) 97.527,40.132 ccw(c97.527,41.665) D1.1@98.611,40.581 ; D1.1@98.791,39.863 ccw(c98.14,39.212) 98.14,40.132 ccw(c98.14,41.052) D1.1@98.791,40.401 ; U2.11@100.965,58.928 ccw(c99.432,58.928) 100.516,60.012 ccw(c101.6,61.096) U2.11@101.6,59.563 ; U2.20@100.965,81.788 ccw(c99.432,81.788) 100.516,82.872 ccw(c101.6,83.956) U2.20@101.6,82.423 ; U2.11@101.219,58.928 ccw(c100.299,58.928) 100.95,59.578 ccw(c101.6,60.229) U2.11@101.6,59.309 ; U2.20@101.219,81.788 ccw(c100.299,81.788) 100.95,82.438 ccw(c101.6,83.089) U2.20@101.6,82.169
XTAL1: C2.2 U4.19 X1.1 | length 25.6
  Top Layer w0.254: U4.19@70.485,36.068 cw(c68.952,36.068) 70.036,34.984 cw(c71.12,33.9) U4.19@71.12,35.433 ; U4.19@70.739,36.068 cw(c69.819,36.068) 70.47,35.418 cw(c71.12,34.767) U4.19@71.12,35.687 ; U4.19@71.12,36.068 69.875,34.823 69.875,32.233 C2.2@73.152,28.956 ; C2.2@72.644,28.956 ccw(c71.418,28.956) 72.285,29.823 ccw(c73.152,30.69) C2.2@73.152,29.464
  Bottom Layer w0.254: C2.2@73.152,28.956 X1.1@78.232,28.956 ; C2.2@73.511,28.597 cw(c74.378,27.73) 74.378,28.956 cw(c74.378,30.182) C2.2@73.511,29.315 ; X1.1@77.783,28.507 ccw(c76.699,27.423) 76.699,28.956 ccw(c76.699,30.489) X1.1@77.783,29.405 ; X1.1@77.963,28.687 ccw(c77.312,28.036) 77.312,28.956 ccw(c77.312,29.876) X1.1@77.963,29.225
XTAL2: C1.2 U4.18 X1.2 | length 37.9
  Top Layer w0.254: U4.18@71.12,38.608 73.66,38.608 X1.2@83.312,28.956 ; U4.18@71.389,38.339 cw(c72.04,37.688) 72.04,38.608 cw(c72.04,39.528) U4.18@71.389,38.877 ; U4.18@71.569,38.159 cw(c72.653,37.075) 72.653,38.608 cw(c72.653,40.141) U4.18@71.569,39.057 ; X1.2@82.677,28.956 ccw(c81.144,28.956) 82.228,30.04 ccw(c83.312,31.124) X1.2@83.312,29.591 ; X1.2@82.931,28.956 ccw(c82.011,28.956) 82.662,29.606 ccw(c83.312,30.257) X1.2@83.312,29.337
  Bottom Layer w0.254: X1.2@83.312,28.956 84.328,27.94 ; X1.2@83.33,28.575 cw(c83.367,27.792) 83.922,28.346 cw(c84.476,28.901) X1.2@83.693,28.938 ; X1.2@83.342,28.322 cw(c83.403,27.015) 84.328,27.94 ; X1.2@83.946,28.926 ccw(c85.253,28.865) 84.328,27.94 ; C1.2@91.081,27.581 ccw(c90.214,26.714) 90.214,27.94 ccw(c90.214,29.166) C1.2@91.081,28.299 ; C1.2@91.44,27.94 84.328,27.94
Y1: U3.6 U3.10 | length 16.4
  Bottom Layer w0.254: U3.6@54.864,69.088 57.404,71.628 U3.10@62.484,71.628 ; U3.6@54.864,69.469 ccw(c54.864,70.389) 55.514,69.738 ccw(c56.165,69.088) U3.6@55.245,69.088 ; U3.6@54.864,69.723 ccw(c54.864,71.256) 55.948,70.172 ccw(c57.032,69.088) U3.6@55.499,69.088 ; U3.10@62.035,71.179 ccw(c60.951,70.095) 60.951,71.628 ccw(c60.951,73.161) U3.10@62.035,72.077 ; U3.10@62.215,71.359 ccw(c61.564,70.708) 61.564,71.628 ccw(c61.564,72.548) U3.10@62.215,71.897
pads on no net: R2.8 R2.9 U3.3 U3.9 U3.11 U4.7 U4.8 U4.9 U4.25 U4.26 U4.27 U4.28 U4.29 U4.30 U4.31

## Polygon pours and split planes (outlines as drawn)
GND on Top Layer "Top Layer-No Net" (solid, pour order 1000): 25.4,119.38 25.4,25.4 104.14,25.4 104.14,119.38 25.4,119.38
GND on Bottom Layer "Top Layer-No Net" (solid, pour order 1001): 25.4,119.38 104.14,119.38 104.14,25.4 25.4,25.4 25.4,119.38

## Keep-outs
Keep-Out Layer:
  lines w0.254: 25.4,30.48 ccw(c30.48,30.48) 30.48,25.4 99.06,25.4 ccw(c99.06,30.48) 104.14,30.48 104.14,114.3 ccw(c99.06,114.3) 99.06,119.38 30.48,119.38 ccw(c30.48,114.3) 25.4,114.3 25.4,30.48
